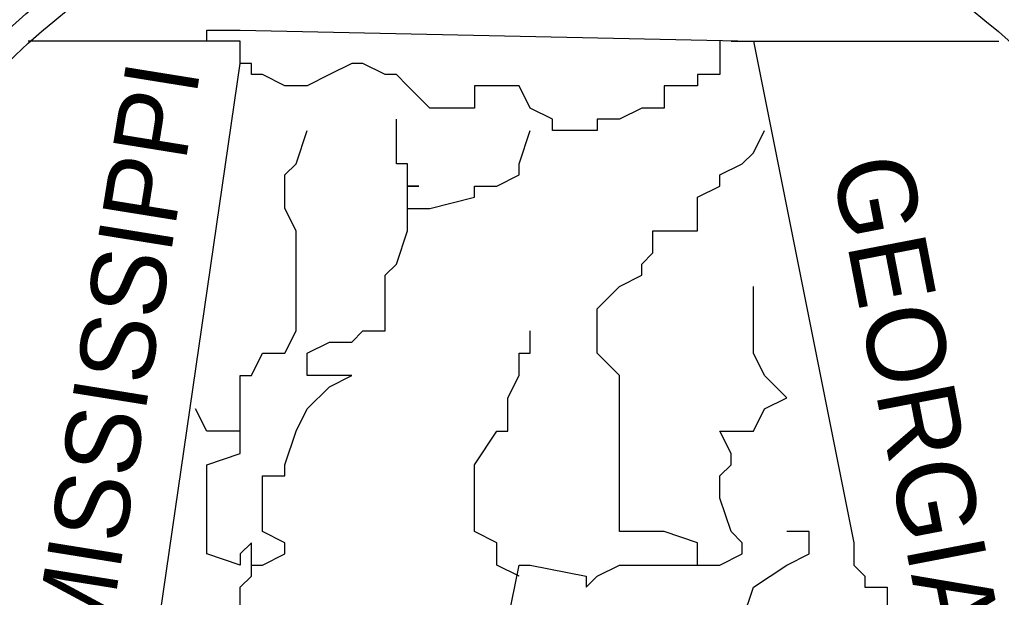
# Model space of a CAD drawing. Extents: x 2193008 to 2198143, y 1236112 to 1237864.
# Drawn here: x 2194695.868 to 2194700.493, y 1237127.982 to 1237130.706 of the extents above; entities that cross this region are included whole.
import ezdxf

# ---------------------------------------------------------------- set-up
doc = ezdxf.new("R2010")
doc.units = 0
doc.layers.add('great seal', color=7, linetype='Continuous')

msp = doc.modelspace()

# ---------------------------------------------------------------- linework, layer by layer
at = {"layer": 'great seal'}
for p, q in [((2194696.9075, 1237130.6045), (2194695.909, 1237130.6045)), ((2194696.9075, 1237130.6045), (2194695.909, 1237130.6045)), ((2194696.9075, 1237130.6045), (2194695.909, 1237130.6045)), ((2194699.2199, 1237130.6045), (2194700.4811, 1237130.6045)), ((2194699.2199, 1237130.6045), (2194700.4811, 1237130.6045)), ((2194699.2199, 1237130.6045), (2194700.4811, 1237130.6045)), ((2194698.2214, 1237128.0819), (2194698.2214, 1237128.0819)), ((2194698.2214, 1237128.0819), (2194698.2214, 1237128.0819)), ((2194698.2214, 1237128.0819), (2194698.2214, 1237128.0819)), ((2194698.2214, 1237128.0819), (2194698.2214, 1237128.0819)), ((2194698.2214, 1237128.0819), (2194698.2214, 1237128.0819)), ((2194698.2214, 1237128.0819), (2194698.2214, 1237128.0819))]:
    msp.add_line(p, q, dxfattribs=at)
for points in [[(2194696.4346, 1237127.2411), (2194696.9075, 1237130.4994), (2194696.9075, 1237130.6045), (2194696.9075, 1237130.6045), (2194696.9075, 1237130.6045), (2194696.7499, 1237130.6045), (2194696.7499, 1237130.657), (2194696.9075, 1237130.657), (2194699.325, 1237130.6045), (2194699.7979, 1237128.2396), (2194699.7979, 1237128.1345), (2194699.8505, 1237128.0819), (2194699.8505, 1237128.0294), (2194699.8505, 1237128.0294), (2194699.9556, 1237128.0294), (2194699.9556, 1237127.8717)], [(2194696.4346, 1237127.2411), (2194696.9075, 1237130.4994), (2194696.9075, 1237130.6045), (2194696.9075, 1237130.6045), (2194696.9075, 1237130.6045), (2194696.7499, 1237130.6045), (2194696.7499, 1237130.657), (2194696.9075, 1237130.657), (2194699.325, 1237130.6045), (2194699.7979, 1237128.2396), (2194699.7979, 1237128.1345), (2194699.8505, 1237128.0819), (2194699.8505, 1237128.0294), (2194699.8505, 1237128.0294), (2194699.9556, 1237128.0294), (2194699.9556, 1237127.8717)], [(2194696.4346, 1237127.2411), (2194696.9075, 1237130.4994), (2194696.9075, 1237130.6045), (2194696.9075, 1237130.6045), (2194696.9075, 1237130.6045), (2194696.7499, 1237130.6045), (2194696.7499, 1237130.657), (2194696.9075, 1237130.657), (2194699.325, 1237130.6045), (2194699.7979, 1237128.2396), (2194699.7979, 1237128.1345), (2194699.8505, 1237128.0819), (2194699.8505, 1237128.0294), (2194699.8505, 1237128.0294), (2194699.9556, 1237128.0294), (2194699.9556, 1237127.8717)], [(2194699.1673, 1237130.6045), (2194699.1673, 1237130.6045), (2194699.1673, 1237130.6045), (2194699.1673, 1237130.4994), (2194699.1673, 1237130.4468), (2194699.1673, 1237130.4468), (2194699.0622, 1237130.4468), (2194699.0622, 1237130.4468), (2194699.0622, 1237130.3942), (2194698.9045, 1237130.3942), (2194698.9045, 1237130.2891), (2194698.7994, 1237130.2891), (2194698.6943, 1237130.2366), (2194698.6418, 1237130.2366), (2194698.5892, 1237130.2366), (2194698.5892, 1237130.184), (2194698.5367, 1237130.184), (2194698.5367, 1237130.184), (2194698.379, 1237130.184), (2194698.379, 1237130.184), (2194698.379, 1237130.2366), (2194698.2739, 1237130.2891), (2194698.2214, 1237130.3942), (2194698.2214, 1237130.3942), (2194698.1163, 1237130.3942), (2194698.0111, 1237130.3942), (2194698.0111, 1237130.2891), (2194697.8009, 1237130.2891), (2194697.6958, 1237130.3942), (2194697.6433, 1237130.4468), (2194697.5907, 1237130.4468), (2194697.4856, 1237130.4994), (2194697.4331, 1237130.4994), (2194697.328, 1237130.4468), (2194697.328, 1237130.4468), (2194697.2229, 1237130.3942), (2194697.1703, 1237130.3942), (2194697.1178, 1237130.3942), (2194697.0126, 1237130.4468), (2194697.0126, 1237130.4468), (2194697.0126, 1237130.4468), (2194696.9601, 1237130.4468), (2194696.9601, 1237130.4468), (2194696.9601, 1237130.4468), (2194696.9601, 1237130.4994), (2194696.9075, 1237130.4994), (2194696.9075, 1237130.6045), (2194696.9075, 1237130.6045), (2194696.9075, 1237130.6045)], [(2194699.1673, 1237130.6045), (2194699.1673, 1237130.6045), (2194699.1673, 1237130.6045), (2194699.1673, 1237130.4994), (2194699.1673, 1237130.4468), (2194699.1673, 1237130.4468), (2194699.0622, 1237130.4468), (2194699.0622, 1237130.4468), (2194699.0622, 1237130.3942), (2194698.9045, 1237130.3942), (2194698.9045, 1237130.2891), (2194698.7994, 1237130.2891), (2194698.6943, 1237130.2366), (2194698.6418, 1237130.2366), (2194698.5892, 1237130.2366), (2194698.5892, 1237130.184), (2194698.5367, 1237130.184), (2194698.5367, 1237130.184), (2194698.379, 1237130.184), (2194698.379, 1237130.184), (2194698.379, 1237130.2366), (2194698.2739, 1237130.2891), (2194698.2214, 1237130.3942), (2194698.2214, 1237130.3942), (2194698.1163, 1237130.3942), (2194698.0111, 1237130.3942), (2194698.0111, 1237130.2891), (2194697.8009, 1237130.2891), (2194697.6958, 1237130.3942), (2194697.6433, 1237130.4468), (2194697.5907, 1237130.4468), (2194697.4856, 1237130.4994), (2194697.4331, 1237130.4994), (2194697.328, 1237130.4468), (2194697.328, 1237130.4468), (2194697.2229, 1237130.3942), (2194697.1703, 1237130.3942), (2194697.1178, 1237130.3942), (2194697.0126, 1237130.4468), (2194697.0126, 1237130.4468), (2194697.0126, 1237130.4468), (2194696.9601, 1237130.4468), (2194696.9601, 1237130.4468), (2194696.9601, 1237130.4468), (2194696.9601, 1237130.4994), (2194696.9075, 1237130.4994), (2194696.9075, 1237130.6045), (2194696.9075, 1237130.6045), (2194696.9075, 1237130.6045)], [(2194699.1673, 1237130.6045), (2194699.1673, 1237130.6045), (2194699.1673, 1237130.6045), (2194699.1673, 1237130.4994), (2194699.1673, 1237130.4468), (2194699.1673, 1237130.4468), (2194699.0622, 1237130.4468), (2194699.0622, 1237130.4468), (2194699.0622, 1237130.3942), (2194698.9045, 1237130.3942), (2194698.9045, 1237130.2891), (2194698.7994, 1237130.2891), (2194698.6943, 1237130.2366), (2194698.6418, 1237130.2366), (2194698.5892, 1237130.2366), (2194698.5892, 1237130.184), (2194698.5367, 1237130.184), (2194698.5367, 1237130.184), (2194698.379, 1237130.184), (2194698.379, 1237130.184), (2194698.379, 1237130.2366), (2194698.2739, 1237130.2891), (2194698.2214, 1237130.3942), (2194698.2214, 1237130.3942), (2194698.1163, 1237130.3942), (2194698.0111, 1237130.3942), (2194698.0111, 1237130.2891), (2194697.8009, 1237130.2891), (2194697.6958, 1237130.3942), (2194697.6433, 1237130.4468), (2194697.5907, 1237130.4468), (2194697.4856, 1237130.4994), (2194697.4331, 1237130.4994), (2194697.328, 1237130.4468), (2194697.328, 1237130.4468), (2194697.2229, 1237130.3942), (2194697.1703, 1237130.3942), (2194697.1178, 1237130.3942), (2194697.0126, 1237130.4468), (2194697.0126, 1237130.4468), (2194697.0126, 1237130.4468), (2194696.9601, 1237130.4468), (2194696.9601, 1237130.4468), (2194696.9601, 1237130.4468), (2194696.9601, 1237130.4994), (2194696.9075, 1237130.4994), (2194696.9075, 1237130.6045), (2194696.9075, 1237130.6045), (2194696.9075, 1237130.6045)], [(2194697.6958, 1237129.8162), (2194697.6958, 1237129.8687), (2194697.6958, 1237129.9213), (2194697.7484, 1237129.9213), (2194697.6958, 1237129.9213), (2194697.6958, 1237129.9738), (2194697.6958, 1237130.0264), (2194697.6433, 1237130.0264), (2194697.6433, 1237130.0789), (2194697.6433, 1237130.184), (2194697.6433, 1237130.2366)], [(2194697.6958, 1237129.8162), (2194697.6958, 1237129.8687), (2194697.6958, 1237129.9213), (2194697.7484, 1237129.9213), (2194697.6958, 1237129.9213), (2194697.6958, 1237129.9738), (2194697.6958, 1237130.0264), (2194697.6433, 1237130.0264), (2194697.6433, 1237130.0789), (2194697.6433, 1237130.184), (2194697.6433, 1237130.2366)], [(2194697.6958, 1237129.8162), (2194697.6958, 1237129.8687), (2194697.6958, 1237129.9213), (2194697.7484, 1237129.9213), (2194697.6958, 1237129.9213), (2194697.6958, 1237129.9738), (2194697.6958, 1237130.0264), (2194697.6433, 1237130.0264), (2194697.6433, 1237130.0789), (2194697.6433, 1237130.184), (2194697.6433, 1237130.2366)], [(2194696.9075, 1237128.7651), (2194696.9075, 1237128.8702), (2194696.9075, 1237128.9228), (2194696.9075, 1237129.0279), (2194696.9601, 1237129.0279), (2194697.0126, 1237129.133), (2194697.1178, 1237129.133), (2194697.1703, 1237129.2381), (2194697.1703, 1237129.4483), (2194697.1703, 1237129.5534), (2194697.1703, 1237129.606), (2194697.1703, 1237129.7111), (2194697.1178, 1237129.8162), (2194697.1178, 1237129.9213), (2194697.1178, 1237129.9738), (2194697.1703, 1237130.0264), (2194697.2229, 1237130.184)], [(2194696.9075, 1237128.7651), (2194696.9075, 1237128.8702), (2194696.9075, 1237128.9228), (2194696.9075, 1237129.0279), (2194696.9601, 1237129.0279), (2194697.0126, 1237129.133), (2194697.1178, 1237129.133), (2194697.1703, 1237129.2381), (2194697.1703, 1237129.4483), (2194697.1703, 1237129.5534), (2194697.1703, 1237129.606), (2194697.1703, 1237129.7111), (2194697.1178, 1237129.8162), (2194697.1178, 1237129.9213), (2194697.1178, 1237129.9738), (2194697.1703, 1237130.0264), (2194697.2229, 1237130.184)], [(2194696.9075, 1237128.7651), (2194696.9075, 1237128.8702), (2194696.9075, 1237128.9228), (2194696.9075, 1237129.0279), (2194696.9601, 1237129.0279), (2194697.0126, 1237129.133), (2194697.1178, 1237129.133), (2194697.1703, 1237129.2381), (2194697.1703, 1237129.4483), (2194697.1703, 1237129.5534), (2194697.1703, 1237129.606), (2194697.1703, 1237129.7111), (2194697.1178, 1237129.8162), (2194697.1178, 1237129.9213), (2194697.1178, 1237129.9738), (2194697.1703, 1237130.0264), (2194697.2229, 1237130.184)], [(2194696.9601, 1237128.1345), (2194696.9601, 1237128.1345), (2194697.0126, 1237128.1345), (2194697.0126, 1237128.1345), (2194697.1178, 1237128.187), (2194697.1178, 1237128.2396), (2194697.0126, 1237128.2921), (2194697.0126, 1237128.2921), (2194697.0126, 1237128.4498), (2194697.0126, 1237128.5549), (2194697.1178, 1237128.5549), (2194697.1178, 1237128.6075), (2194697.1703, 1237128.7651), (2194697.2229, 1237128.8702), (2194697.328, 1237128.9753), (2194697.4331, 1237129.0279), (2194697.328, 1237129.0279), (2194697.2229, 1237129.0279), (2194697.2229, 1237129.133), (2194697.328, 1237129.1855), (2194697.328, 1237129.1855), (2194697.4331, 1237129.1855), (2194697.4856, 1237129.2381), (2194697.4856, 1237129.2381), (2194697.5907, 1237129.2381), (2194697.5907, 1237129.3432), (2194697.5907, 1237129.4483), (2194697.5907, 1237129.4483), (2194697.5907, 1237129.5008), (2194697.6433, 1237129.5534), (2194697.6958, 1237129.7111), (2194697.6958, 1237129.7111), (2194697.6958, 1237129.8162), (2194697.7484, 1237129.8162), (2194697.8009, 1237129.8162), (2194697.8009, 1237129.8162), (2194698.0111, 1237129.8687), (2194698.0111, 1237129.9213), (2194698.1163, 1237129.9213), (2194698.2214, 1237129.9738), (2194698.2214, 1237130.0264), (2194698.2739, 1237130.184)], [(2194696.9601, 1237128.1345), (2194696.9601, 1237128.1345), (2194697.0126, 1237128.1345), (2194697.0126, 1237128.1345), (2194697.1178, 1237128.187), (2194697.1178, 1237128.2396), (2194697.0126, 1237128.2921), (2194697.0126, 1237128.2921), (2194697.0126, 1237128.4498), (2194697.0126, 1237128.5549), (2194697.1178, 1237128.5549), (2194697.1178, 1237128.6075), (2194697.1703, 1237128.7651), (2194697.2229, 1237128.8702), (2194697.328, 1237128.9753), (2194697.4331, 1237129.0279), (2194697.328, 1237129.0279), (2194697.2229, 1237129.0279), (2194697.2229, 1237129.133), (2194697.328, 1237129.1855), (2194697.328, 1237129.1855), (2194697.4331, 1237129.1855), (2194697.4856, 1237129.2381), (2194697.4856, 1237129.2381), (2194697.5907, 1237129.2381), (2194697.5907, 1237129.3432), (2194697.5907, 1237129.4483), (2194697.5907, 1237129.4483), (2194697.5907, 1237129.5008), (2194697.6433, 1237129.5534), (2194697.6958, 1237129.7111), (2194697.6958, 1237129.7111), (2194697.6958, 1237129.8162), (2194697.7484, 1237129.8162), (2194697.8009, 1237129.8162), (2194697.8009, 1237129.8162), (2194698.0111, 1237129.8687), (2194698.0111, 1237129.9213), (2194698.1163, 1237129.9213), (2194698.2214, 1237129.9738), (2194698.2214, 1237130.0264), (2194698.2739, 1237130.184)], [(2194696.9601, 1237128.1345), (2194696.9601, 1237128.1345), (2194697.0126, 1237128.1345), (2194697.0126, 1237128.1345), (2194697.1178, 1237128.187), (2194697.1178, 1237128.2396), (2194697.0126, 1237128.2921), (2194697.0126, 1237128.2921), (2194697.0126, 1237128.4498), (2194697.0126, 1237128.5549), (2194697.1178, 1237128.5549), (2194697.1178, 1237128.6075), (2194697.1703, 1237128.7651), (2194697.2229, 1237128.8702), (2194697.328, 1237128.9753), (2194697.4331, 1237129.0279), (2194697.328, 1237129.0279), (2194697.2229, 1237129.0279), (2194697.2229, 1237129.133), (2194697.328, 1237129.1855), (2194697.328, 1237129.1855), (2194697.4331, 1237129.1855), (2194697.4856, 1237129.2381), (2194697.4856, 1237129.2381), (2194697.5907, 1237129.2381), (2194697.5907, 1237129.3432), (2194697.5907, 1237129.4483), (2194697.5907, 1237129.4483), (2194697.5907, 1237129.5008), (2194697.6433, 1237129.5534), (2194697.6958, 1237129.7111), (2194697.6958, 1237129.7111), (2194697.6958, 1237129.8162), (2194697.7484, 1237129.8162), (2194697.8009, 1237129.8162), (2194697.8009, 1237129.8162), (2194698.0111, 1237129.8687), (2194698.0111, 1237129.9213), (2194698.1163, 1237129.9213), (2194698.2214, 1237129.9738), (2194698.2214, 1237130.0264), (2194698.2739, 1237130.184)], [(2194699.0622, 1237128.1345), (2194699.0622, 1237128.2396), (2194698.9045, 1237128.2921), (2194698.852, 1237128.2921), (2194698.6943, 1237128.2921), (2194698.6943, 1237128.5549), (2194698.6943, 1237128.5549), (2194698.6943, 1237128.6075), (2194698.6943, 1237128.7651), (2194698.6943, 1237128.8702), (2194698.6943, 1237129.0279), (2194698.5892, 1237129.133), (2194698.5892, 1237129.3432), (2194698.6943, 1237129.4483), (2194698.7994, 1237129.5008), (2194698.7994, 1237129.5534), (2194698.852, 1237129.606), (2194698.852, 1237129.7111), (2194699.0622, 1237129.7111), (2194699.0622, 1237129.8162), (2194699.0622, 1237129.8687), (2194699.1673, 1237129.9213), (2194699.1673, 1237129.9738), (2194699.2724, 1237130.0264), (2194699.325, 1237130.0789), (2194699.3775, 1237130.184)], [(2194699.0622, 1237128.1345), (2194699.0622, 1237128.2396), (2194698.9045, 1237128.2921), (2194698.852, 1237128.2921), (2194698.6943, 1237128.2921), (2194698.6943, 1237128.5549), (2194698.6943, 1237128.5549), (2194698.6943, 1237128.6075), (2194698.6943, 1237128.7651), (2194698.6943, 1237128.8702), (2194698.6943, 1237129.0279), (2194698.5892, 1237129.133), (2194698.5892, 1237129.3432), (2194698.6943, 1237129.4483), (2194698.7994, 1237129.5008), (2194698.7994, 1237129.5534), (2194698.852, 1237129.606), (2194698.852, 1237129.7111), (2194699.0622, 1237129.7111), (2194699.0622, 1237129.8162), (2194699.0622, 1237129.8687), (2194699.1673, 1237129.9213), (2194699.1673, 1237129.9738), (2194699.2724, 1237130.0264), (2194699.325, 1237130.0789), (2194699.3775, 1237130.184)], [(2194699.0622, 1237128.1345), (2194699.0622, 1237128.2396), (2194698.9045, 1237128.2921), (2194698.852, 1237128.2921), (2194698.6943, 1237128.2921), (2194698.6943, 1237128.5549), (2194698.6943, 1237128.5549), (2194698.6943, 1237128.6075), (2194698.6943, 1237128.7651), (2194698.6943, 1237128.8702), (2194698.6943, 1237129.0279), (2194698.5892, 1237129.133), (2194698.5892, 1237129.3432), (2194698.6943, 1237129.4483), (2194698.7994, 1237129.5008), (2194698.7994, 1237129.5534), (2194698.852, 1237129.606), (2194698.852, 1237129.7111), (2194699.0622, 1237129.7111), (2194699.0622, 1237129.8162), (2194699.0622, 1237129.8687), (2194699.1673, 1237129.9213), (2194699.1673, 1237129.9738), (2194699.2724, 1237130.0264), (2194699.325, 1237130.0789), (2194699.3775, 1237130.184)], [(2194698.1688, 1237127.8717), (2194698.2214, 1237128.1345), (2194698.2739, 1237128.1345), (2194698.5367, 1237128.0819), (2194698.5367, 1237128.0294), (2194698.5892, 1237128.0819), (2194698.6943, 1237128.1345), (2194698.852, 1237128.1345), (2194699.0622, 1237128.1345), (2194699.1673, 1237128.1345), (2194699.2724, 1237128.187), (2194699.2724, 1237128.2396), (2194699.2199, 1237128.2921), (2194699.2199, 1237128.2921), (2194699.1673, 1237128.4498), (2194699.1673, 1237128.5549), (2194699.2199, 1237128.6075), (2194699.2199, 1237128.66), (2194699.1673, 1237128.7651), (2194699.325, 1237128.7651), (2194699.3775, 1237128.8702), (2194699.4826, 1237128.9228), (2194699.3775, 1237129.0279), (2194699.3775, 1237129.0279), (2194699.325, 1237129.133), (2194699.325, 1237129.2381), (2194699.325, 1237129.4483)], [(2194698.1688, 1237127.8717), (2194698.2214, 1237128.1345), (2194698.2739, 1237128.1345), (2194698.5367, 1237128.0819), (2194698.5367, 1237128.0294), (2194698.5892, 1237128.0819), (2194698.6943, 1237128.1345), (2194698.852, 1237128.1345), (2194699.0622, 1237128.1345), (2194699.1673, 1237128.1345), (2194699.2724, 1237128.187), (2194699.2724, 1237128.2396), (2194699.2199, 1237128.2921), (2194699.2199, 1237128.2921), (2194699.1673, 1237128.4498), (2194699.1673, 1237128.5549), (2194699.2199, 1237128.6075), (2194699.2199, 1237128.66), (2194699.1673, 1237128.7651), (2194699.325, 1237128.7651), (2194699.3775, 1237128.8702), (2194699.4826, 1237128.9228), (2194699.3775, 1237129.0279), (2194699.3775, 1237129.0279), (2194699.325, 1237129.133), (2194699.325, 1237129.2381), (2194699.325, 1237129.4483)], [(2194698.1688, 1237127.8717), (2194698.2214, 1237128.1345), (2194698.2739, 1237128.1345), (2194698.5367, 1237128.0819), (2194698.5367, 1237128.0294), (2194698.5892, 1237128.0819), (2194698.6943, 1237128.1345), (2194698.852, 1237128.1345), (2194699.0622, 1237128.1345), (2194699.1673, 1237128.1345), (2194699.2724, 1237128.187), (2194699.2724, 1237128.2396), (2194699.2199, 1237128.2921), (2194699.2199, 1237128.2921), (2194699.1673, 1237128.4498), (2194699.1673, 1237128.5549), (2194699.2199, 1237128.6075), (2194699.2199, 1237128.66), (2194699.1673, 1237128.7651), (2194699.325, 1237128.7651), (2194699.3775, 1237128.8702), (2194699.4826, 1237128.9228), (2194699.3775, 1237129.0279), (2194699.3775, 1237129.0279), (2194699.325, 1237129.133), (2194699.325, 1237129.2381), (2194699.325, 1237129.4483)], [(2194698.2214, 1237128.0819), (2194698.1163, 1237128.1345), (2194698.1163, 1237128.187), (2194698.1163, 1237128.2396), (2194698.0111, 1237128.2921), (2194698.0111, 1237128.4498), (2194698.0111, 1237128.5549), (2194698.0111, 1237128.6075), (2194698.0111, 1237128.6075), (2194698.1163, 1237128.7651), (2194698.1688, 1237128.7651), (2194698.1688, 1237128.9228), (2194698.2214, 1237129.0279), (2194698.2214, 1237129.0279), (2194698.2214, 1237129.133), (2194698.2739, 1237129.133), (2194698.2739, 1237129.2381)], [(2194698.2214, 1237128.0819), (2194698.1163, 1237128.1345), (2194698.1163, 1237128.187), (2194698.1163, 1237128.2396), (2194698.0111, 1237128.2921), (2194698.0111, 1237128.4498), (2194698.0111, 1237128.5549), (2194698.0111, 1237128.6075), (2194698.0111, 1237128.6075), (2194698.1163, 1237128.7651), (2194698.1688, 1237128.7651), (2194698.1688, 1237128.9228), (2194698.2214, 1237129.0279), (2194698.2214, 1237129.0279), (2194698.2214, 1237129.133), (2194698.2739, 1237129.133), (2194698.2739, 1237129.2381)], [(2194698.2214, 1237128.0819), (2194698.1163, 1237128.1345), (2194698.1163, 1237128.187), (2194698.1163, 1237128.2396), (2194698.0111, 1237128.2921), (2194698.0111, 1237128.4498), (2194698.0111, 1237128.5549), (2194698.0111, 1237128.6075), (2194698.0111, 1237128.6075), (2194698.1163, 1237128.7651), (2194698.1688, 1237128.7651), (2194698.1688, 1237128.9228), (2194698.2214, 1237129.0279), (2194698.2214, 1237129.0279), (2194698.2214, 1237129.133), (2194698.2739, 1237129.133), (2194698.2739, 1237129.2381)], [(2194696.9075, 1237127.8192), (2194696.9075, 1237128.0294), (2194696.9075, 1237128.0294), (2194696.9601, 1237128.0819), (2194696.9601, 1237128.1345), (2194696.9601, 1237128.2396), (2194696.9075, 1237128.187), (2194696.9075, 1237128.1345), (2194696.7499, 1237128.187), (2194696.7499, 1237128.2396), (2194696.7499, 1237128.2921), (2194696.7499, 1237128.2921), (2194696.7499, 1237128.5549), (2194696.7499, 1237128.5549), (2194696.7499, 1237128.6075), (2194696.9075, 1237128.66), (2194696.9075, 1237128.7651), (2194696.7499, 1237128.7651), (2194696.6973, 1237128.8702), (2194696.6973, 1237128.8702)], [(2194696.9075, 1237127.8192), (2194696.9075, 1237128.0294), (2194696.9075, 1237128.0294), (2194696.9601, 1237128.0819), (2194696.9601, 1237128.1345), (2194696.9601, 1237128.2396), (2194696.9075, 1237128.187), (2194696.9075, 1237128.1345), (2194696.7499, 1237128.187), (2194696.7499, 1237128.2396), (2194696.7499, 1237128.2921), (2194696.7499, 1237128.2921), (2194696.7499, 1237128.5549), (2194696.7499, 1237128.5549), (2194696.7499, 1237128.6075), (2194696.9075, 1237128.66), (2194696.9075, 1237128.7651), (2194696.7499, 1237128.7651), (2194696.6973, 1237128.8702), (2194696.6973, 1237128.8702)], [(2194696.9075, 1237127.8192), (2194696.9075, 1237128.0294), (2194696.9075, 1237128.0294), (2194696.9601, 1237128.0819), (2194696.9601, 1237128.1345), (2194696.9601, 1237128.2396), (2194696.9075, 1237128.187), (2194696.9075, 1237128.1345), (2194696.7499, 1237128.187), (2194696.7499, 1237128.2396), (2194696.7499, 1237128.2921), (2194696.7499, 1237128.2921), (2194696.7499, 1237128.5549), (2194696.7499, 1237128.5549), (2194696.7499, 1237128.6075), (2194696.9075, 1237128.66), (2194696.9075, 1237128.7651), (2194696.7499, 1237128.7651), (2194696.6973, 1237128.8702), (2194696.6973, 1237128.8702)], [(2194698.5367, 1237126.7156), (2194698.5367, 1237126.7156), (2194698.5367, 1237126.8732), (2194698.5892, 1237126.9258), (2194698.5892, 1237126.9783), (2194698.5892, 1237127.0834), (2194698.6418, 1237127.0834), (2194698.6943, 1237127.1885), (2194698.852, 1237127.2411), (2194698.9045, 1237127.3462), (2194699.0622, 1237127.3462), (2194699.0622, 1237127.4513), (2194699.1673, 1237127.6615), (2194699.1673, 1237127.7666), (2194699.1673, 1237127.7666), (2194699.1673, 1237127.8192), (2194699.2199, 1237127.8192), (2194699.2724, 1237127.8717), (2194699.325, 1237128.0294), (2194699.4826, 1237128.1345), (2194699.5877, 1237128.187), (2194699.5877, 1237128.2396), (2194699.5877, 1237128.2921), (2194699.4826, 1237128.2921)], [(2194698.5367, 1237126.7156), (2194698.5367, 1237126.7156), (2194698.5367, 1237126.8732), (2194698.5892, 1237126.9258), (2194698.5892, 1237126.9783), (2194698.5892, 1237127.0834), (2194698.6418, 1237127.0834), (2194698.6943, 1237127.1885), (2194698.852, 1237127.2411), (2194698.9045, 1237127.3462), (2194699.0622, 1237127.3462), (2194699.0622, 1237127.4513), (2194699.1673, 1237127.6615), (2194699.1673, 1237127.7666), (2194699.1673, 1237127.7666), (2194699.1673, 1237127.8192), (2194699.2199, 1237127.8192), (2194699.2724, 1237127.8717), (2194699.325, 1237128.0294), (2194699.4826, 1237128.1345), (2194699.5877, 1237128.187), (2194699.5877, 1237128.2396), (2194699.5877, 1237128.2921), (2194699.4826, 1237128.2921)], [(2194698.5367, 1237126.7156), (2194698.5367, 1237126.7156), (2194698.5367, 1237126.8732), (2194698.5892, 1237126.9258), (2194698.5892, 1237126.9783), (2194698.5892, 1237127.0834), (2194698.6418, 1237127.0834), (2194698.6943, 1237127.1885), (2194698.852, 1237127.2411), (2194698.9045, 1237127.3462), (2194699.0622, 1237127.3462), (2194699.0622, 1237127.4513), (2194699.1673, 1237127.6615), (2194699.1673, 1237127.7666), (2194699.1673, 1237127.7666), (2194699.1673, 1237127.8192), (2194699.2199, 1237127.8192), (2194699.2724, 1237127.8717), (2194699.325, 1237128.0294), (2194699.4826, 1237128.1345), (2194699.5877, 1237128.187), (2194699.5877, 1237128.2396), (2194699.5877, 1237128.2921), (2194699.4826, 1237128.2921)]]:
    msp.add_lwpolyline(points, dxfattribs=at)
for radius in [4.5988, 4.5988, 4.5988, 4.4778, 4.4778, 4.4778, 3.5557, 3.5557, 3.5557, 3.4444, 3.4444, 3.4444]:
    msp.add_circle((2194698.2249, 1237128.0451), radius, dxfattribs=at)

# ---------------------------------------------------------------- texts
for s, height, rotation, p in [('A', 1.1695, 323.9887, (2194700.0082, 1237131.1825)), ('A', 1.1695, 323.9887, (2194700.0082, 1237131.1825)), ('A', 1.1695, 323.9887, (2194700.0082, 1237131.1825)), ('MISSISSIPPI', 0.350947, 80.8531, (2194696.2769, 1237127.7141)), ('MISSISSIPPI', 0.350947, 80.8531, (2194696.2769, 1237127.7141)), ('MISSISSIPPI', 0.350947, 80.8531, (2194696.2769, 1237127.7141)), ('GEORGIA', 0.36892, 280.9296, (2194699.6928, 1237130.0264)), ('GEORGIA', 0.36892, 280.9296, (2194699.6928, 1237130.0264)), ('GEORGIA', 0.36892, 280.9296, (2194699.6928, 1237130.0264))]:
    msp.add_text(s, height=height, rotation=rotation, dxfattribs=at).set_placement(p)

doc.saveas('drawing.dxf')
